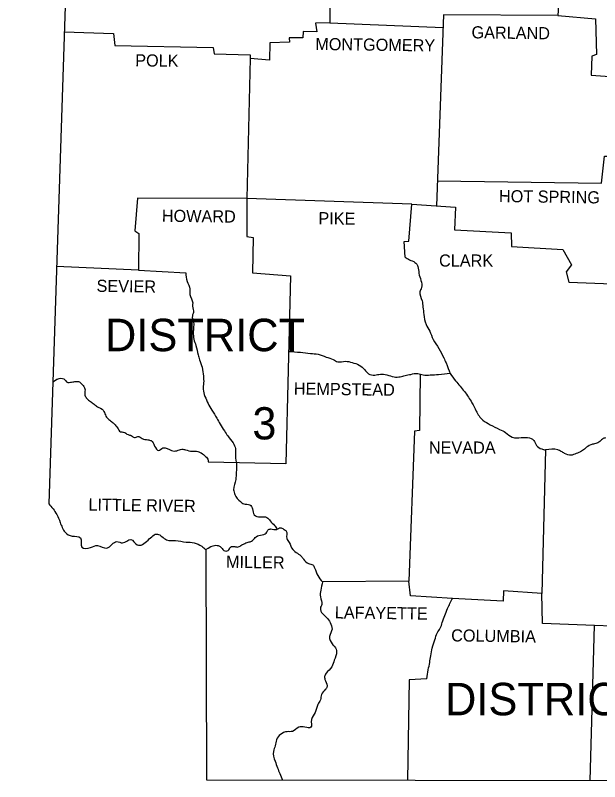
# Model space of a CAD drawing. Extents: x -0.3 to 2.65, y 0 to 1.9.
# Drawn here: x 1.0951 to 1.1888, y 0.5736 to 0.6965 of the extents above; entities that cross this region are included whole.
import ezdxf

# ---------------------------------------------------------------- set-up
doc = ezdxf.new("R2010")
doc.units = 0
doc.layers.add('Default', color=7, linetype='Continuous')

msp = doc.modelspace()

# ---------------------------------------------------------------- linework, layer by layer
at = {"layer": 'Default'}
msp.add_line((1.10185, 0.63817), (1.10109, 0.63769), dxfattribs=at)
for points in [[(1.09511, 0.81784), (1.10455, 0.74198), (1.10045, 0.61817)], [(1.14558, 0.71393), (1.14552, 0.69525), (1.14321, 0.6952), (1.14342, 0.69385), (1.14122, 0.69387), (1.14116, 0.69286), (1.13901, 0.69286), (1.13906, 0.69216), (1.1359, 0.69206), (1.13582, 0.68928), (1.13274, 0.68957), (1.13222, 0.66711)], [(1.19734, 0.70186), (1.18245, 0.7023), (1.18204, 0.69644), (1.16375, 0.69655), (1.16263, 0.66592)], [(1.18204, 0.69644), (1.18808, 0.69592), (1.18826, 0.69017), (1.18751, 0.68993), (1.18741, 0.68687), (1.19337, 0.68643), (1.19337, 0.68392), (1.19734, 0.68371), (1.19742, 0.68122), (1.19835, 0.68106), (1.19832, 0.67745)], [(1.14552, 0.69525), (1.16368, 0.69454)], [(1.10295, 0.69382), (1.11082, 0.69356), (1.11103, 0.69164), (1.1268, 0.69131), (1.12698, 0.69032), (1.13274, 0.69014), (1.13274, 0.68957)], [(1.16278, 0.66994), (1.18904, 0.66955), (1.18953, 0.67391), (1.19161, 0.67388), (1.19166, 0.67754), (1.20149, 0.67741), (1.20144, 0.6752), (1.20398, 0.67502), (1.20395, 0.67103), (1.20561, 0.67087)], [(1.15867, 0.6662), (1.13222, 0.66711), (1.11466, 0.66714), (1.11427, 0.66192), (1.11489, 0.66148), (1.11487, 0.65562), (1.10171, 0.65622)], [(1.13222, 0.66711), (1.13222, 0.66104), (1.13323, 0.66086), (1.13312, 0.65521), (1.13919, 0.65471), (1.13844, 0.62458), (1.12604, 0.62486)], [(1.15758, 0.65772), (1.15745, 0.66024), (1.1582, 0.66029), (1.15867, 0.6662), (1.16567, 0.66571), (1.16552, 0.66211), (1.17457, 0.66161), (1.17465, 0.65943), (1.18284, 0.65894), (1.18424, 0.65648), (1.18339, 0.65536), (1.1838, 0.65368), (1.2047, 0.65291)], [(1.11487, 0.65562), (1.12241, 0.65521)], [(1.15999, 0.63897), (1.15989, 0.62992), (1.15906, 0.62982), (1.15815, 0.60578)], [(1.18009, 0.62681), (1.1795, 0.60378), (1.17335, 0.60422), (1.1733, 0.60253), (1.16519, 0.603)], [(1.12566, 0.61083), (1.12576, 0.5739), (1.29301, 0.57362)], [(1.16519, 0.603), (1.15846, 0.60339), (1.15815, 0.60578), (1.14433, 0.60565)], [(1.19908, 0.59823), (1.17962, 0.59896), (1.1795, 0.60378)], [(1.1879, 0.59865), (1.18721, 0.5738)], [(1.16106, 0.59011), (1.15825, 0.58993), (1.15795, 0.57385)]]:
    msp.add_lwpolyline(points, dxfattribs=at)
for points in [[(1.15758, 0.65772), (1.15828, 0.65728), (1.15916, 0.65687), (1.15963, 0.65619), (1.15979, 0.65513), (1.16012, 0.65399), (1.1602, 0.65282), (1.15994, 0.65217), (1.1603, 0.65072), (1.16043, 0.64971), (1.16059, 0.64854), (1.16093, 0.64693), (1.16152, 0.64584), (1.16207, 0.64452), (1.16298, 0.64307), (1.16378, 0.64154), (1.16414, 0.64074), (1.16482, 0.63905), (1.16567, 0.63788), (1.16707, 0.63615), (1.16829, 0.63436), (1.16897, 0.63303), (1.17003, 0.63158), (1.17122, 0.63085), (1.17273, 0.6301), (1.17369, 0.62961), (1.17475, 0.62883), (1.17618, 0.62878), (1.17721, 0.62878), (1.1782, 0.62834), (1.17864, 0.62753), (1.17947, 0.62696), (1.18009, 0.62681)], [(1.12241, 0.65521), (1.12265, 0.65383), (1.12306, 0.65261), (1.12309, 0.65173), (1.12353, 0.65036), (1.1235, 0.64986), (1.12366, 0.64883), (1.12348, 0.64831), (1.12368, 0.64722), (1.12366, 0.64636), (1.12363, 0.64569), (1.12371, 0.64455), (1.12405, 0.64354), (1.12441, 0.64206), (1.12464, 0.64125), (1.12503, 0.64006), (1.12524, 0.63861), (1.12529, 0.63755), (1.12521, 0.63653), (1.1255, 0.63539), (1.12599, 0.63425), (1.12662, 0.63316), (1.12739, 0.63192), (1.12794, 0.63093), (1.12861, 0.62989), (1.12916, 0.62904), (1.13001, 0.62792), (1.13038, 0.62702), (1.13038, 0.62577), (1.13056, 0.62455), (1.13051, 0.62326), (1.13043, 0.62204), (1.13009, 0.62043), (1.1303, 0.61965), (1.13118, 0.61851), (1.13172, 0.61817), (1.13268, 0.61799), (1.13312, 0.61734), (1.13341, 0.61641), (1.13437, 0.61607), (1.13543, 0.61599), (1.13595, 0.61542), (1.13663, 0.6147), (1.13704, 0.61409)], [(1.13889, 0.6426), (1.1408, 0.64245), (1.14241, 0.64227), (1.14363, 0.64214), (1.1449, 0.64169), (1.14607, 0.64128), (1.14679, 0.64094), (1.14801, 0.64102), (1.14907, 0.64081), (1.15024, 0.6404), (1.15112, 0.63962), (1.15169, 0.63902), (1.15273, 0.63879), (1.15361, 0.63895), (1.15465, 0.63884), (1.15582, 0.63851), (1.1568, 0.63853), (1.15758, 0.63871), (1.15849, 0.63892), (1.1596, 0.63905), (1.16046, 0.63884), (1.1616, 0.63882), (1.16295, 0.63892), (1.16478, 0.63912)], [(1.10185, 0.63817), (1.10286, 0.63819), (1.10351, 0.6376), (1.10395, 0.63765), (1.10465, 0.63775), (1.10538, 0.6377), (1.10584, 0.63729), (1.10626, 0.63659), (1.10623, 0.63589), (1.10626, 0.6356), (1.10659, 0.63503), (1.10714, 0.63456), (1.10774, 0.63412), (1.10825, 0.63373), (1.10919, 0.63316), (1.10929, 0.63298), (1.10963, 0.63223), (1.1101, 0.63166), (1.11064, 0.63127), (1.11124, 0.63065), (1.1115, 0.63036), (1.11196, 0.62971), (1.11246, 0.62966), (1.11318, 0.62925), (1.11367, 0.62912), (1.11419, 0.62878), (1.11474, 0.62896), (1.11544, 0.62865), (1.11635, 0.62842), (1.11686, 0.62829), (1.11743, 0.62743), (1.11806, 0.6267), (1.11876, 0.62712), (1.12016, 0.6267), (1.12101, 0.62668), (1.12179, 0.62691), (1.12239, 0.62683), (1.12348, 0.62658), (1.12415, 0.62658), (1.1249, 0.62632), (1.12558, 0.62577), (1.12602, 0.62515), (1.12604, 0.62486)], [(1.18969, 0.62875), (1.18922, 0.62855), (1.18865, 0.62805), (1.18795, 0.62779), (1.18733, 0.62761), (1.18647, 0.62707), (1.18587, 0.6266), (1.18499, 0.62621), (1.18416, 0.62595), (1.18315, 0.62624), (1.18261, 0.62655), (1.18204, 0.62681), (1.18009, 0.62681)], [(1.10045, 0.61817), (1.10174, 0.61646), (1.10229, 0.61519), (1.10309, 0.61361), (1.10421, 0.61299), (1.10553, 0.61273), (1.10579, 0.6112), (1.10716, 0.61114), (1.10828, 0.61148), (1.10978, 0.61107), (1.11139, 0.61213), (1.1123, 0.6119), (1.1136, 0.61244), (1.11463, 0.61159), (1.11637, 0.61234), (1.1179, 0.61332), (1.11935, 0.61239), (1.12078, 0.61226), (1.12247, 0.61203), (1.12379, 0.61192), (1.12498, 0.61135), (1.12566, 0.61083)], [(1.12566, 0.61083), (1.12724, 0.61151), (1.12796, 0.6113), (1.12853, 0.6107), (1.12923, 0.61068), (1.1296, 0.61122), (1.13027, 0.6113), (1.13082, 0.61125), (1.13141, 0.61159), (1.13191, 0.61182), (1.13258, 0.61205), (1.1331, 0.61226), (1.13354, 0.61275), (1.1344, 0.61314), (1.13533, 0.61348), (1.13559, 0.61395), (1.13606, 0.61413), (1.13696, 0.61407), (1.13759, 0.61433), (1.13808, 0.6141), (1.13852, 0.61379), (1.13862, 0.61262), (1.13899, 0.61197), (1.13956, 0.61083), (1.14031, 0.61024), (1.14103, 0.60964), (1.14129, 0.60928), (1.1421, 0.60858), (1.14277, 0.60837), (1.14308, 0.60788), (1.14358, 0.60666), (1.14433, 0.60565)], [(1.14433, 0.60565), (1.14407, 0.6043), (1.14399, 0.60323), (1.14422, 0.60204), (1.14399, 0.60142), (1.14435, 0.60056), (1.14505, 0.59989), (1.14555, 0.59916), (1.14586, 0.59807), (1.14547, 0.59691), (1.14591, 0.59569), (1.14633, 0.59522), (1.14658, 0.59447), (1.14622, 0.59309), (1.14583, 0.59203), (1.14492, 0.59099), (1.14467, 0.59047), (1.1448, 0.5898), (1.14503, 0.58871), (1.14477, 0.58837), (1.1442, 0.5876), (1.14399, 0.58674), (1.14358, 0.58599), (1.14316, 0.58469), (1.14256, 0.58358), (1.14246, 0.58233), (1.14153, 0.58236), (1.14052, 0.58233), (1.13953, 0.58168), (1.13867, 0.58163), (1.13761, 0.58119), (1.13696, 0.58033), (1.13676, 0.57937), (1.13647, 0.57847), (1.13673, 0.57691), (1.13714, 0.57582), (1.13748, 0.57494), (1.13792, 0.57388)], [(1.16106, 0.59011), (1.16129, 0.59156), (1.16152, 0.59273), (1.16168, 0.59379), (1.16194, 0.59504), (1.16235, 0.59636), (1.16272, 0.59745), (1.16321, 0.59823), (1.16352, 0.59914), (1.16393, 0.60025), (1.16438, 0.60137), (1.16519, 0.603)]]:
    msp.add_spline(points, degree=3, dxfattribs=at)

# ---------------------------------------------------------------- texts
for s, height, rotation, p in [('GARLAND', 0.001945, 359.2717, (1.16821, 0.69279)), ('MONTGOMERY', 0.001945, 359.2707, (1.14317, 0.69092)), ('POLK', 0.001945, 359.3233, (1.11431, 0.6883)), ('HOT SPRING', 0.001945, 359.1956, (1.17261, 0.66654)), ('HOWARD', 0.001945, 359.303, (1.11858, 0.66338)), ('PIKE', 0.001945, 359.1737, (1.14367, 0.66299)), ('SEVIER', 0.001945, 359.1815, (1.10811, 0.65215)), ('HEMPSTEAD', 0.001945, 359.2571, (1.13973, 0.63568)), ('LITTLE RIVER', 0.0019451, 359.2076, (1.10681, 0.61708)), ('MILLER', 0.001945, 359.1885, (1.12886, 0.60791)), ('LAFAYETTE', 0.001945, 359.2511, (1.1463, 0.59979)), ('COLUMBIA', 0.001945, 359.2105, (1.16495, 0.59611))]:
    msp.add_text(s, height=height, rotation=rotation, dxfattribs=at).set_placement(p)
for s, height, p in [('CLARK', 0.001945, (1.16302, 0.65619)), ('DISTRICT', 0.005203, (1.10947, 0.64263)), ('3', 0.00516, (1.13311, 0.62849)), ('NEVADA', 0.001945, (1.16139, 0.62621)), ('DISTRICT 7', 0.005203, (1.16397, 0.58426))]:
    msp.add_text(s, height=height, dxfattribs=at).set_placement(p)

doc.saveas('drawing.dxf')
